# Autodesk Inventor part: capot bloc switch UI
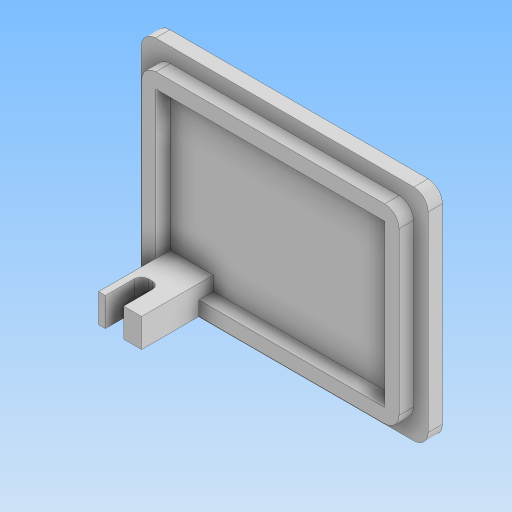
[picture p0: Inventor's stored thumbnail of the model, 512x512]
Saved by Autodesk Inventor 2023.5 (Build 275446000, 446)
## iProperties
Created: 2025-12
Part Number: capot bloc switch UI
Material: Générique
Document SubType Name: Modeling
Designer: admin
Density: 1 g/cm^3
Appearance: Par défaut
Author: admin
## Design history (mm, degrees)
sketch "Esquisse1"
  geometry: L1 (-20, 15.324)-(20, 15.324); L2 (20, 15.324)-(20, -15.324); L3 (20, -15.324)-(-20, -15.324); L4 (-20, -15.324)-(-20, 15.324); 1 further point
  constraints: 8 end point, 2 parallel, 1 horizontal, 1 perpendicular
  dimensions: "d0" = 40 distance of L2.end L3.end; "d1" = 20 distance from line of point (0, 0) L4; "d2" = 30.648 distance of L3.end L1.start; "d3" = 15.324 distance from line of point (0, 0) L1 (= 0.5 x d2)
extrude "Extrusion1" new body sketch "Esquisse1" distance "d4" = 2; taper "d5" = 0 deg
sketch "Esquisse2"
  geometry: L1 (-17.95, 13.274)-(17.95, 13.274); L2 (17.95, 13.274)-(17.95, -13.274); L3 (17.95, -13.274)-(-17.95, -13.274); L4 (-17.95, -13.274)-(-17.95, 13.274); L5 (-20, 15.324)-(-20, -15.324) reference; L6 (-20, -15.324)-(20, -15.324) reference; L7 (20, -15.324)-(20, 15.324) reference; L8 (20, 15.324)-(-20, 15.324) reference; L9 (-15.95, 11.179)-(15.95, 11.179); L10 (15.95, 11.179)-(15.95, -11.274); L11 (15.95, -11.274)-(-15.95, -11.274); L12 (-15.95, -11.274)-(-15.95, 11.179); 1 further point
  constraints: 16 end point, 4 parallel, 2 horizontal, 2 perpendicular
  dimensions: "d6" = 2.05 distance between parallel lines of L5 L4; "d7" = 2.05 distance between parallel lines of L6 L3; "d8" = 2.05 distance between parallel lines of L7 L2; "d9" = 2.05 distance between parallel lines of L8 L1; "d10" = 2 distance between parallel lines of L4 L12; "d11" = 2 distance between parallel lines of L2 L10; "d12" = 2.09509 distance between parallel lines of L1 L9; "d13" = 2 distance between parallel lines of L3 L11
extrude "Extrusion2" join sketch "Esquisse2" distance "d14" = 2; taper "d15" = 0 deg
fillet "Congé1" dims "d16" = 2
sketch "Esquisse3"
  geometry: L1 (15.95, -11.274)-(-15.95, -11.274) reference; L2 (-15.95, -13.274)-(15.95, -13.274) reference; L3 (-15.95, -11.274)-(-9.95, -11.274); L4 (-9.95, -11.274)-(-9.95, -13.274); L5 (-9.95, -13.274)-(-15.95, -13.274); L6 (-15.95, -13.274)-(-15.95, -11.274); 3 further points
  constraints: 8 end point, 2 parallel, 1 horizontal, 1 perpendicular, 1 point on line
  dimensions: "d17" = 6 distance between parallel lines of L6 L4
extrude "Extrusion3" join sketch "Esquisse3" distance "d18" = 8; taper "d19" = 0 deg
sketch "Esquisse4"
  geometry: L1 (6, 10)-(0, 10) reference; L2 (0.95, 10)-(3.5, 10); L3 (3.5, 10)-(3.5, 5); L4 (3.5, 5)-(0.95, 5); L5 (0.95, 5)-(0.95, 10); L6 (-2, 2)-(-2, 0) reference; L7 (-2.05, 0)-(33.95, 0) reference; 2 further points
  constraints: 8 end point, 2 parallel, 1 horizontal, 1 perpendicular, 1 point on line
  dimensions: "d20" = 2.95 distance between parallel lines of L5 L6; "d21" = 2.55 distance of L3.end L4.end; "d22" = 5 distance between parallel lines of L7 L4
extrude "Extrusion4" cut sketch "Esquisse4" distance "d23" = 5; taper "d24" = 0 deg
fillet "Congé2" dims "d25" = 1
sketch "Esquisse5"
  geometry: L1 (0.95, -10)-(0.95, -6) reference; L2 (1.95, -5)-(2.5, -5) reference; L3 (3.5, -6)-(3.5, -10) reference; L4 (6, -10)-(3.5, -10) reference; L5 (6, -2)-(6, -10) reference; L6 (31.9, -2)-(6, -2) reference; L7 (31.9, 0)-(31.9, -2) reference; L8 (0, 0)-(31.9, 0) reference; L9 (0, 0)-(0, -2) reference; L10 (0, -2)-(0, -10) reference; L11 (0.95, -10)-(0, -10) reference; L12 (6, -2)-(6, 0); L13 (-2.05, 0)-(33.95, 0) reference; A1 r 1 centre (1.95, -6) between (1.95, -5) and (0.95, -6) reference; A2 r 1 centre (2.5, -6) between (3.5, -6) and (2.5, -5) reference; 2 further points
  constraints: 2 end point, 1 perpendicular, 1 point on line
extrude "Extrusion5" join sketch "Esquisse5" distance "d26" = 2; taper "d27" = 0 deg
node "Solide1"
node "Boucle projetée1"
